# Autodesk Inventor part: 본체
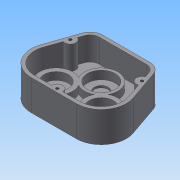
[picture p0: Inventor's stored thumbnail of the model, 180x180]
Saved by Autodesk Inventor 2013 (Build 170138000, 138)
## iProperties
Created: 2014-12
Part Number: 본체
Material: 일반
Document SubType Name: Modeling
Designer: WINDOWS7
Density: 1 g/cm^3
Author: WINDOWS7
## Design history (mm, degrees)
sketch "스케치1" dims "d16" = 46
  geometry: L1 (-47, 36)-(47, 36); L2 (47, 36)-(66.565, -20.803); L3 (32.527, -68.527)-(-32.527, -68.527); L4 (-66.565, -20.803)-(-47, 36); L5 (-32.527, -32.527)-(0, 0); L6 (0, 0)-(32.527, -32.527); L7 (0, 0)-(-87.158, 0); A1 r 36 centre (-32.527, -32.527) between (-32.527, -68.527) and (-66.565, -20.803); A2 r 36 centre (32.527, -32.527) between (66.565, -20.803) and (32.527, -68.527); 2 further points
  constraints: 14 end point, 4 point on circle, 4 tangent, 2 centre point, 2 horizontal, 2 midpoint, 2 vertical alignment, 1 coincident, 1 equal radius, 1 parallel, 3 other
  dimensions: "d8" = 94 distance of L1.start L1.end; "d11" = 36 distance from line of L5.end L1; "d12" = 36 radius of A1; "d13" = 90 deg angle of L6 L5; "d18" = 45 deg angle of L7 L5
extrude "돌출1" new body sketch "스케치1" distance "d19" = 44; taper "d20" = 0 deg
fillet "모깎기1" dims "d21" = 18
sketch "스케치2"
  geometry: L1 (-51.181, 23.862)-(-66.565, -20.803) reference; L2 (-32.527, -68.527)-(32.527, -68.527) reference; L3 (66.565, -20.803)-(51.181, 23.862) reference; L4 (34.162, 36)-(-34.162, 36) reference; L5 (-46.453, 22.233)-(-61.837, -22.432); L6 (-32.527, -63.527)-(32.527, -63.527); L7 (61.837, -22.432)-(46.453, 22.233); L8 (34.162, 31)-(-34.162, 31); A1 r 18 centre (-34.162, 18) between (-34.162, 36) and (-51.181, 23.862) reference; A2 r 36 centre (-32.527, -32.527) between (-66.565, -20.803) and (-32.527, -68.527) reference; A3 r 36 centre (32.527, -32.527) between (32.527, -68.527) and (66.565, -20.803) reference; A4 r 18 centre (34.162, 18) between (51.181, 23.862) and (34.162, 36) reference; A5 r 13 centre (-34.162, 18) between (-34.162, 31) and (-46.453, 22.233); A6 r 31 centre (-32.527, -32.527) between (-61.837, -22.432) and (-32.527, -63.527); A7 r 31 centre (32.527, -32.527) between (32.527, -63.527) and (61.837, -22.432); A8 r 13 centre (34.162, 18) between (46.453, 22.233) and (34.162, 31); 1 further point
  constraints: 8 end point, 8 point on circle, 4 centre point, 7 other
  dimensions: "d22" = 5 distance between parallel lines of L4 L8
extrude "돌출2" cut sketch "스케치2" distance "d23" = 34; taper "d24" = 0 deg
sketch "스케치3"
  geometry: C1 r 24 at (0, 0); C2 r 24 at (-32.527, -32.527); C3 r 24 at (32.527, -32.527); A1 r 31 centre (-32.527, -32.527) between (-61.837, -22.432) and (-32.527, -63.527) reference; A2 r 31 centre (32.527, -32.527) between (32.527, -63.527) and (61.837, -22.432) reference; 1 further point
  constraints: 3 centre point, 3 coincident, 1 equal radius
  dimensions: "d25" = 48 diameter of C1; "d27" = 48 diameter of C3
extrude "돌출3" join sketch "스케치3" distance "d28" = 11; taper "d29" = 0 deg
sketch "스케치4"
  geometry: C1 r 20 at (0, 0); A1 r 24 centre (0, 0) between (21.111, -11.416) and (-21.111, -11.416) reference
  constraints: 1 centre point, 1 coincident
  dimensions: "d30" = 40 diameter of C1
extrude "돌출4" cut sketch "스케치4" distance "d32" = 12; taper "d33" = 0 deg
sketch "스케치5"
  geometry: C1 r 17.5 at (-32.527, -32.527); C2 r 17.5 at (32.527, -32.527); A1 r 24 centre (32.527, -32.527) between (11.416, -21.111) and (21.111, -11.416) reference; A2 r 24 centre (-32.527, -32.527) between (-21.111, -11.416) and (-11.416, -21.111) reference
  constraints: 2 centre point, 2 coincident, 1 equal radius
  dimensions: "d34" = 35 diameter of C2
extrude "돌출5" cut sketch "스케치5" distance "d36" = 11; taper "d37" = 0 deg
sketch "스케치6"
  geometry: C1 r 20 at (0, 0) reference; C2 r 10 at (0, 0)
  constraints: 1 centre point, 1 coincident
  dimensions: "d38" = 20 diameter of C2
extrude "돌출6" cut sketch "스케치6" distance "d40" = 3; taper "d41" = 0 deg
sketch "스케치7"
  geometry: C1 r 20 at (-32.527, -32.527); C2 r 20 at (32.527, -32.527); A1 r 36 centre (-32.527, -32.527) between (-66.565, -20.803) and (-32.527, -68.527) reference; A2 r 36 centre (32.527, -32.527) between (32.527, -68.527) and (66.565, -20.803) reference; 1 further point
  constraints: 2 centre point, 2 coincident, 1 equal radius
  dimensions: "d42" = 40 diameter of C1
extrude "돌출7" join sketch "스케치7" distance "d44" = 7; taper "d45" = 0 deg
sketch "스케치8"
  geometry: C1 r 20 at (0, 0) reference; C2 r 15 at (0, 0); C3 r 20 at (65.054, 0) reference; C4 r 15 at (65.054, 0); 1 further point
  constraints: 2 centre point, 2 coincident, 1 equal radius
  dimensions: "d46" = 30 diameter of C2
extrude "돌출8" cut sketch "스케치8" distance "d48" = 7; taper "d49" = 0 deg
sketch "스케치9"
  geometry: C1 r 15 at (0, 0) reference; C2 r 7.75 at (0, 0); C3 r 15 at (65.054, 0) reference; C4 r 7.75 at (65.054, 0); 1 further point
  constraints: 2 centre point, 2 coincident, 1 equal radius
  dimensions: "d50" = 15.5 diameter of C2
extrude "돌출9" cut sketch "스케치9" distance "d52" = 10; taper "d53" = 0 deg
sketch "스케치10"
  geometry: L1 (-61.837, -22.432)-(-46.453, 22.233) reference; L2 (46.453, 22.233)-(61.837, -22.432) reference; L3 (32.527, -63.527)-(-32.527, -63.527) reference; L4 (-51.181, 23.862)-(-66.565, -20.803) reference; L5 (-32.527, -68.527)-(32.527, -68.527) reference; L6 (66.565, -20.803)-(51.181, 23.862) reference; L7 (34.162, 36)-(-34.162, 36) reference; A1 r 8 centre (-51.7, 7) between (-58.461, 2.724) and (-54.394, 14.533); A2 r 8 centre (51.7, 7) between (54.394, 14.533) and (58.461, 2.724); A3 r 8 centre (0, -63.527) between (6.245, -68.527) and (-6.245, -68.527); 1 further point
  constraints: 8 point on line, 6 point on circle, 3 centre point, 2 equal radius, 1 horizontal alignment, 1 midpoint
  dimensions: "d54" = 29 distance from line of L7 A2.centre; "d55" = 8 radius of A2
extrude "돌출10" join sketch "스케치10" distance "d56" = 44; taper "d57" = 0 deg
sketch "스케치11"
  geometry: A1 r 8 centre (-51.7, 7) between (-54.305, -0.564) and (-49.095, 14.564) reference; A2 r 8 centre (51.7, 7) between (49.095, 14.564) and (54.305, -0.564) reference; A3 r 8 centre (0, -63.527) between (8, -63.527) and (-8, -63.527) reference; 4 further points
  constraints: 3 coincident
hole "구멍1" sketch "스케치11" at (-51.7, 7), (51.7, 7), (0, -63.527) diameter "d58" = 4.134; stored, may be unused: countersink angle "d62" = 90 deg, drill point angle "d64" = 118 deg; dims "d59" = 20, "d60" = 4, "d61" = 2, "d63" = 23
sketch "스케치12"
  geometry: L1 (-34.162, 36)-(34.162, 36) reference; 3 further points
  constraints: 1 midpoint, 1 vertical alignment, 1 other
  dimensions: "d65" = 30 distance from line of L1 point (0, 6)
extrude "돌출11" join sketch "스케치12" distance "d66" = 1; taper "d67" = 0 deg
node "솔리드1"
node "투영된 루프1"
